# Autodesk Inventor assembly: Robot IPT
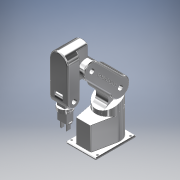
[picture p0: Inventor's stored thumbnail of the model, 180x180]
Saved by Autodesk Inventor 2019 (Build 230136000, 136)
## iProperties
Created: 2018-07
Part Number: Robot IPT
Document SubType Name: Assembly
Designer: Power User
Mass: 35329.7 g
Surface Area: 8047.72 cm^2
Volume: 13085.1 cm^3
Density: 2.7 g/cm^3
Author: Power User
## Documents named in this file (10)
- D:\Karntarat T\06.MFG_Autodesk Inventor file\03.Project Test_byKarn\Practics\Robot IPT\Robot IPT.iam
- D:\Karntarat T\06.MFG_Autodesk Inventor file\03.Project Test_byKarn\Practics\Robot IPT\Robot-Base-Model-A.ipt
- D:\Karntarat T\06.MFG_Autodesk Inventor file\03.Project Test_byKarn\Practics\Robot IPT\Robot-Axis1-1.ipt
- D:\Karntarat T\06.MFG_Autodesk Inventor file\03.Project Test_byKarn\Practics\Robot IPT\Robot-Axis1-2.ipt
- D:\Karntarat T\06.MFG_Autodesk Inventor file\03.Project Test_byKarn\Practics\Robot IPT\Robot-Axis1-3.ipt
- D:\Karntarat T\06.MFG_Autodesk Inventor file\03.Project Test_byKarn\Practics\Robot IPT\Robot-Axis1-4.ipt
- D:\Karntarat T\06.MFG_Autodesk Inventor file\03.Project Test_byKarn\Practics\Robot IPT\Robot-Axis1-5.ipt
- D:\Karntarat T\06.MFG_Autodesk Inventor file\03.Project Test_byKarn\Practics\Robot IPT\Robot-Axis1-6.ipt
- D:\Karntarat T\06.MFG_Autodesk Inventor file\03.Project Test_byKarn\Practics\Robot IPT\Robot-Clamp.ipt
- D:\Karntarat T\06.MFG_Autodesk Inventor file\03.Project Test_byKarn\Practics\Robot IPT\Robot-Clamp-Mount.ipt
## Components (10 placed, 9 different names)
1. Robot-Base-Model-A:1 — Angle:1
2. Robot-Axis1-1:1 — Insert:2, Flush:4
3. Robot-Axis1-2:1 — Insert:2, Insert:3, Angle:1, Angle:2
4. Robot-Clamp:1 — Mate:5, Mate:6, Flush:2
5. Robot-Clamp-Mount:1 — Mate:3, Mate:4, Flush:1, Mate:5, Mate:6, Flush:2
6. Robot-Axis1-3:1 — Insert:3, Insert:4, Angle:2, Flush:3
7. Robot-Axis1-4:1 — Insert:4, Insert:5, Mate:7, Flush:3
8. Robot-Axis1-5:1 — Insert:5, Mate:1, Mate:2
9. Robot-Axis1-6:1 — Mate:1, Mate:2, Mate:7
10. Robot-Clamp:2 — Mate:3, Mate:4, Flush:1
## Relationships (17: Mate 7, Insert 4, Flush 4, Angle 2)
- Insert:2: Robot-Axis1-1:1 ↔ Robot-Axis1-2:1
- Insert:3: Robot-Axis1-2:1 ↔ Robot-Axis1-3:1
- Insert:4: Robot-Axis1-3:1 ↔ Robot-Axis1-4:1
- Insert:5: Robot-Axis1-4:1 ↔ Robot-Axis1-5:1
- Mate:1: Robot-Axis1-5:1 ↔ Robot-Axis1-6:1
- Mate:2: Robot-Axis1-5:1 ↔ Robot-Axis1-6:1
- Mate:3: Robot-Clamp-Mount:1 ↔ Robot-Clamp:2
- Mate:4: Robot-Clamp-Mount:1 ↔ Robot-Clamp:2
- Flush:1: Robot-Clamp-Mount:1 ↔ Robot-Clamp:2
- Mate:5: Robot-Clamp:1 ↔ Robot-Clamp-Mount:1
- Mate:6: Robot-Clamp:1 ↔ Robot-Clamp-Mount:1
- Flush:2: Robot-Clamp:1 ↔ Robot-Clamp-Mount:1
- Angle:1: Robot-Base-Model-A:1 ↔ Robot-Axis1-2:1
- Angle:2: Robot-Axis1-2:1 ↔ Robot-Axis1-3:1
- Mate:7: Robot-Axis1-4:1 ↔ Robot-Axis1-6:1
- Flush:3: Robot-Axis1-3:1 ↔ Robot-Axis1-4:1
- Flush:4: Robot-Axis1-1:1
